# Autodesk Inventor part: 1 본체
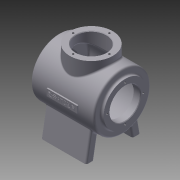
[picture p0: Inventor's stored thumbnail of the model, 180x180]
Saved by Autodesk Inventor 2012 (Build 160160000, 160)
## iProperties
Created: 2015-01
Part Number: 1 본체
Material: 알루미늄-6061
Document SubType Name: Modeling
Designer: Owner
Mass: 1021.13 g
Surface Area: 1060.1 cm^2
Volume: 376.801 cm^3
Density: 2.71 g/cm^3
Author: Owner
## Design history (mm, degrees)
sketch "스케치1"
  geometry: L1 (-61, 0)-(61, 0); L2 (-49, 27)-(-49, 45); L3 (-49, 45)-(48, 45); L4 (48, 45)-(48, 27); L5 (48, 27)-(60, 27); L6 (60, 27)-(60, 38); L7 (60, 38)-(55, 38); L8 (55, 38)-(55, 50); L9 (55, 50)-(-57, 50); L10 (-57, 50)-(-57, 38); L11 (-57, 38)-(-62, 38); L12 (-62, 38)-(-62, 27); L13 (-49, 27)-(-62, 27); 2 further points
  constraints: 26 end point, 5 parallel, 1 coincident, 1 horizontal, 1 horizontal alignment, 1 midpoint, 1 perpendicular
  dimensions: "d0" = 122 distance of L1.start L1.end; "d2" = 90 diameter of L3 L1; "d3" = 54 diameter of L5 L1; "d4" = 76 diameter of L6.end L1; "d5" = 100 diameter of L9 L1; "d6" = 112 distance of L8.end L9.end; "d7" = 60 horizontal distance of L6.end point (0, 0); "d9" = 5 distance of L6.end L7.end; "d75" = 12 distance between parallel lines of L4 L6; "d76" = 97 distance of L2.end L3.end; "d77" = 76 diameter of L11 L1; "d78" = 62 distance from line of L12 point (0, 0); "d79" = 54 diameter of L13 L1
revolve "회전1" sketch "스케치1" stored, may be unused: angle "d11" = 90 deg
node "작업 평면2"
  node "작업 평면1"
sketch "스케치2"
  geometry: C1 r 38 at (-1, 0); 1 further point
  constraints: 1 centre point, 1 coincident
  dimensions: "d13" = 76 diameter of C1
extrude "돌출1" join sketch "스케치2" stored distance "d14" = 10; taper "d15" = 0 deg
sketch "스케치3"
  geometry: C1 r 38 at (0, 0) reference; C2 r 27 at (0, 0)
  constraints: 1 centre point, 1 coincident
  dimensions: "d16" = 54 diameter of C2
extrude "돌출2" cut sketch "스케치3" stored distance "d17" = 10; taper "d18" = 0 deg
sketch "스케치4" dims "d19" = 64
  geometry: C1 r 27 at (0, 0) reference; C2 r 38 at (0, 0) reference; 2 further points
  constraints: 2 vertical alignment, 1 coincident, 2 other
hole "구멍1" sketch "스케치4" at (0, 32) diameter "d20" = 3.242; stored, may be unused: countersink angle "d24" = 90 deg, drill point angle "d26" = 118 deg; dims "d21" = 8, "d22" = 4, "d23" = 2, "d25" = 10
sketch "스케치5" dims "d30" = 64
  geometry: C1 r 27 at (0, 0) reference; C2 r 38 at (0, 0) reference; 2 further points
  constraints: 2 vertical alignment, 1 coincident, 2 other
hole "구멍2" sketch "스케치5" at (0, 32) diameter "d31" = 3.242; stored, may be unused: countersink angle "d35" = 90 deg, drill point angle "d37" = 118 deg; dims "d32" = 8, "d33" = 4, "d34" = 2, "d36" = 10
sketch "스케치6" dims "d41" = 64
  geometry: C1 r 38 at (0, 0) reference; C2 r 27 at (0, 0) reference; 2 further points
  constraints: 2 vertical alignment, 1 coincident, 2 other
hole "구멍3" sketch "스케치6" at (0, 32) diameter "d42" = 3.242; stored, may be unused: countersink angle "d46" = 90 deg, drill point angle "d48" = 118 deg; dims "d43" = 8, "d44" = 4, "d45" = 2, "d47" = 10
node "작업 평면3"
sketch "스케치7"
  geometry: L1 (-39.336, -30.865)-(-48, -80); L2 (-48, -80)-(-34, -80); L3 (-34, -80)-(-27.282, -41.901); A1 r 50 centre (0, 0) between (-39.336, -30.865) and (-27.282, -41.901) reference; 1 further point
  constraints: 6 end point, 2 point on circle, 1 horizontal, 1 parallel
  dimensions: "d53" = 100 deg angle of L2 L1; "d54" = 14 distance of L1.end L2.end; "d55" = 80 distance from line of L2 point (0, 0); "d56" = 48 horizontal distance of point (0, 0) L1.end
extrude "돌출3" join sketch "스케치7" stored distance "d57" = 80; taper "d58" = 0 deg
node "작업 평면6"
  node "작업 평면5"
sketch "스케치9"
  geometry: L1 (-26, 6)-(28, 6); L2 (28, 6)-(28, -6); L3 (28, -6)-(-26, -6); L4 (-26, -6)-(-26, 6); L5 (28, -6)-(-26, 6); 2 further points
  constraints: 10 end point, 2 parallel, 1 coincident, 1 horizontal, 1 midpoint, 1 perpendicular
  dimensions: "d63" = 54 distance of L2.end L3.end; "d64" = 12 distance of L1.end L2.end
extrude "돌출4" join sketch "스케치9" stored distance "d65" = 80; taper "d66" = 0 deg
node "작업 평면7"
sketch "스케치10"
  geometry: 2 further points
  constraints: 1 coincident, 1 other
feature "엠보싱1" sketch "스케치10" dims "d68" = 0.5, "d69" = 0
chamfer "모따기1" distance "d70" = 1; stored, may be unused: second distance "d71" = 2, angle "d72" = 45 deg
fillet "모깎기1" dims "d73" = 3
fillet "모깎기2" dims "d74" = 3
node "솔리드1"
pattern_circular "원형 패턴1" dims angle "d28" = 360 deg
pattern_circular "원형 패턴2" dims angle "d39" = 360 deg
pattern_circular "원형 패턴3" dims angle "d50" = 360 deg
mirror "대칭1"
other parameters: "d12" = 12, "d52" = -61, "d62" = 2
